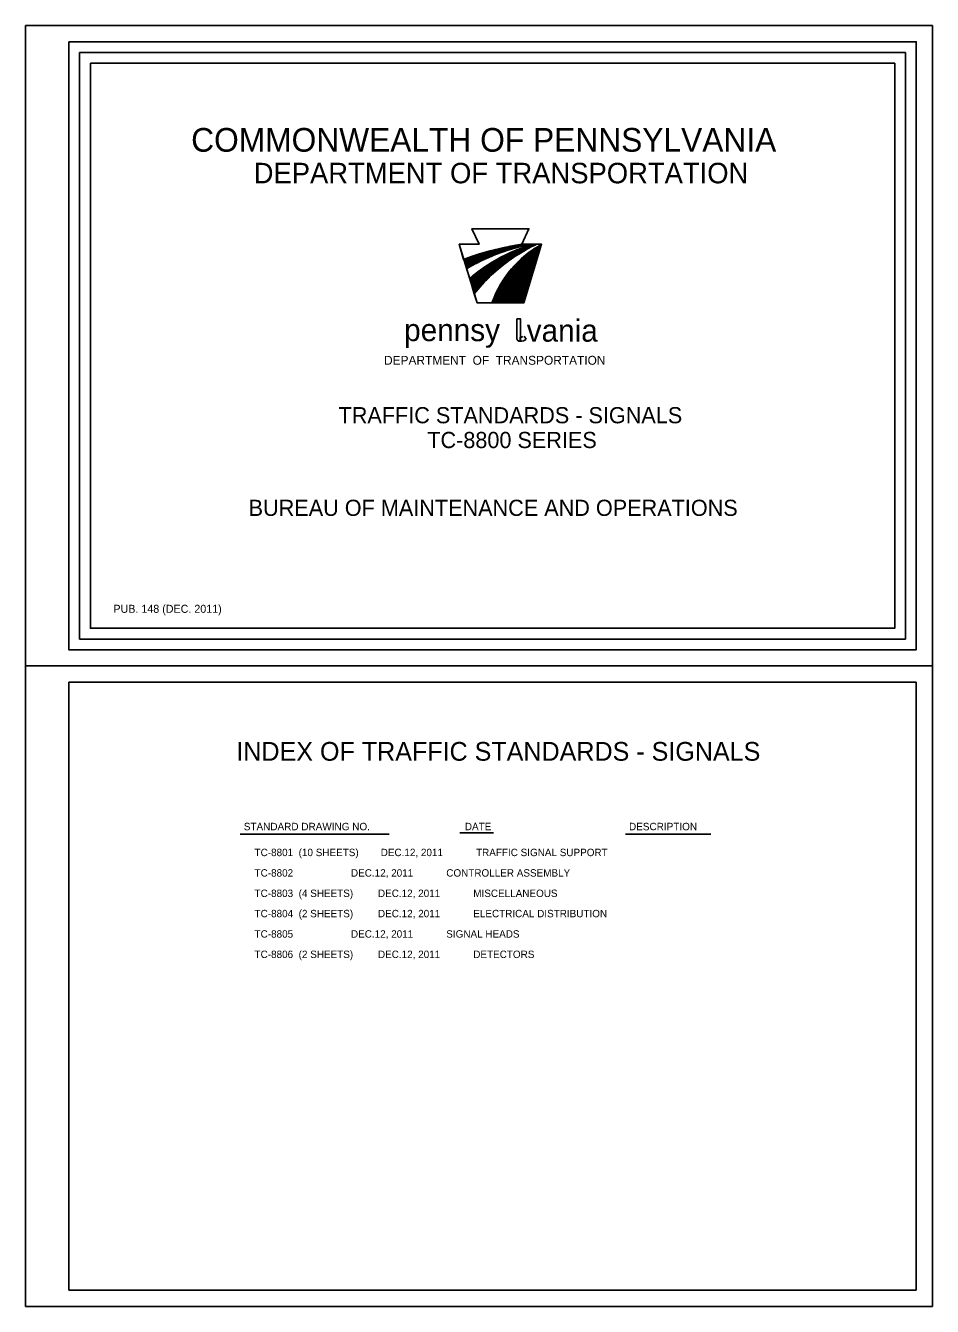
# Model space of a CAD drawing. Extents: x -1746 to -905, y 22 to 1210.
import ezdxf

# ---------------------------------------------------------------- set-up
doc = ezdxf.new("R2010")
doc.units = 0
for name, color, linetype in [('1', 7, 'Continuous'), ('2', 7, 'Continuous'), ('PLT-BNDY', 7, 'Continuous')]:
    doc.layers.add(name, color=color, linetype=linetype)

msp = doc.modelspace()

# ---------------------------------------------------------------- linework, layer by layer
at = {"layer": '1'}
for p, q in [((-1325.5, 1007.3), (-1332.2, 1021.7)), ((-1332.2, 1021.7), (-1279.3, 1021.7)), ((-1279.3, 1021.7), (-1286, 1007.3)), ((-1327.3, 952.9), (-1344, 1007.3)), ((-1344, 1007.3), (-1325.5, 1007.3)), ((-1286, 1007.3), (-1267.6, 1007.3)), ((-1267.6, 1007.3), (-1284.2, 952.9)), ((-1284.2, 952.9), (-1327.3, 952.9)), ((-1706.1, 601.2), (-920.1, 601.2)), ((-1706.1, 37.2), (-1706.1, 601.2)), ((-920.1, 601.2), (-920.1, 37.2)), ((-920.1, 37.2), (-1706.1, 37.2))]:
    msp.add_line(p, q, dxfattribs=at)
for points in [[(-1706.1, 1195.2), (-920.1, 1195.2), (-920.1, 631.2), (-1706.1, 631.2)], [(-1696.1, 1185.2), (-930.1, 1185.2), (-930.1, 641.2), (-1696.1, 641.2)], [(-1686.1, 1175.2), (-940.1, 1175.2), (-940.1, 651.2), (-1686.1, 651.2)], [(-1286, 1007.3), (-1279.3, 1021.7), (-1332.2, 1021.7), (-1325.5, 1007.3), (-1344, 1007.3), (-1340.1, 993.2), (-1332.6, 996), (-1326.2, 998.1), (-1320.9, 999.7), (-1315.2, 1001.2), (-1311, 1002.3), (-1302.4, 1004.3), (-1293.9, 1006), (-1288.6, 1006.8)], [(-1286, 1007.3), (-1289.7, 1006.7), (-1293.9, 1005.9), (-1299, 1004.9), (-1303.4, 1004), (-1308.4, 1002.9), (-1314.9, 1001.2), (-1321.6, 999.4), (-1327.3, 997.6), (-1333.2, 995.7), (-1338, 993.9), (-1339.8, 993.2), (-1337, 984.8), (-1332.7, 987.4), (-1328, 989.8), (-1324.3, 991.7), (-1319.8, 993.9), (-1315.3, 995.8), (-1310.4, 997.8), (-1306.5, 999.3), (-1301.8, 1001), (-1297.2, 1002.4), (-1291.9, 1004), (-1287.6, 1005.2), (-1282.8, 1006.3), (-1279.5, 1007.3)], [(-1279.5, 1007.3), (-1288.1, 1005.1), (-1299.7, 1001.6), (-1309.4, 998.2), (-1318, 994.7), (-1327.6, 990.2), (-1335.1, 986.1), (-1337.3, 984.8), (-1334.2, 975.5), (-1329.9, 979.3), (-1326.8, 981.7), (-1322.8, 984.5), (-1319.5, 986.8), (-1315.6, 989.3), (-1311, 992), (-1305.3, 995.3), (-1300.1, 997.9), (-1294.3, 1000.7), (-1291, 1001.9), (-1286.4, 1003.8), (-1280.6, 1005.7), (-1275.9, 1007.3)], [(-1275.9, 1007.3), (-1281, 1005.6), (-1285.3, 1004.1), (-1290.3, 1002.1), (-1295.5, 1000), (-1300.7, 997.6), (-1306.6, 994.5), (-1312.4, 991.2), (-1317.6, 988), (-1322.4, 984.9), (-1327.4, 981.1), (-1331.1, 978.3), (-1334.2, 975.5), (-1330.1, 961.5), (-1324.9, 967.6), (-1320.4, 972.5), (-1316.2, 976.7), (-1311.3, 981.5), (-1307.1, 985), (-1302.4, 988.9), (-1297.7, 992.5), (-1293.5, 995.4), (-1288.8, 998.3), (-1284.1, 1001.1), (-1280.8, 1003.1), (-1276.6, 1005.4), (-1272.2, 1007.3)], [(-1272.2, 1007.3), (-1276.2, 1005.6), (-1282, 1002.5), (-1289.2, 998.1), (-1297.3, 992.7), (-1304.2, 987.5), (-1308, 984.4), (-1314.3, 978.7), (-1318.1, 974.9), (-1323.2, 969.5), (-1326.5, 965.7), (-1330.1, 961.5), (-1327.3, 952.9), (-1313.4, 952.9), (-1312.6, 955.3), (-1309.9, 961.9), (-1308.2, 965.3), (-1305.3, 970.7), (-1302.6, 975), (-1299, 980.1), (-1295.4, 984.5), (-1290.7, 989.7), (-1286, 994.3), (-1281.9, 997.6), (-1278.1, 1000.7), (-1274.4, 1003.2), (-1270.2, 1005.7), (-1267.6, 1007.3)], [(-1267.6, 1007.3), (-1270.7, 1005.4), (-1274.1, 1003.3), (-1278, 1000.6), (-1282.5, 997.1), (-1286.2, 994.1), (-1289, 991.3), (-1292.4, 987.6), (-1296.4, 983.3), (-1299.7, 979.1), (-1302.6, 975), (-1305.1, 970.9), (-1307, 967.6), (-1309.5, 962.9), (-1312, 956.5), (-1313.4, 952.9), (-1284.2, 952.9)]]:
    msp.add_lwpolyline(points, close=True, dxfattribs=at)
msp.add_circle((-1294.1, 965.8), 6.84, dxfattribs=at)
for centre, radius, start, end in [((-1243, 732.1), 278.5, 98.8803, 110.3962), ((-1239.2, 816.6), 194.6, 102.171, 120.2393), ((-1230.7, 854.8), 159.1, 106.6298, 130.6117), ((-1204.9, 863.2), 159, 115.3724, 141.7165), ((-1219.7, 920.2), 99.4, 118.798, 160.3663)]:
    msp.add_arc(centre, radius, start, end, dxfattribs=at)
at = {"layer": '2'}
for p, q in [((-1338.9, 990.4), (-1325.5, 998.2)), ((-1338.5, 989.5), (-1321.2, 999.5)), ((-1338.2, 988.5), (-1317.4, 1000.5)), ((-1337.9, 987.5), (-1313.6, 1001.5)), ((-1337.6, 986.5), (-1310, 1002.5)), ((-1337.3, 985.6), (-1306.6, 1003.3)), ((-1334, 974.7), (-1279.5, 1006.1)), ((-1333.8, 975.9), (-1284.3, 1004.5)), ((-1333.7, 973.7), (-1275.4, 1007.3)), ((-1333.4, 972.7), (-1282.3, 1002.2)), ((-1329.2, 979.7), (-1290.5, 1002.1)), ((-1326.9, 990.4), (-1303.5, 1003.9)), ((-1322.7, 984.6), (-1298, 998.9)), ((-1316.2, 995.4), (-1300.2, 1004.7)), ((-1309.4, 998.2), (-1297.1, 1005.3)), ((-1303.9, 1000.2), (-1294.1, 1005.9)), ((-1299.2, 1001.8), (-1291.2, 1006.4)), ((-1296.4, 983.3), (-1270.3, 998.3)), ((-1295, 1003.1), (-1288.3, 1006.9)), ((-1294.2, 985.7), (-1269.9, 999.7)), ((-1292, 988.1), (-1269.4, 1001.1)), ((-1290.9, 1004.3), (-1285.6, 1007.3)), ((-1289.6, 990.6), (-1269, 1002.5)), ((-1287, 1005.4), (-1283.6, 1007.3)), ((-1287, 993.3), (-1268.6, 1003.9)), ((-1283.7, 1006.1), (-1281.6, 1007.3)), ((-1282.9, 996.8), (-1268.2, 1005.3)), ((-1279.8, 1003.6), (-1273.4, 1007.3)), ((-1279.6, 1007.3), (-1279.6, 1007.3)), ((-1276.1, 1001.9), (-1267.7, 1006.7)), ((-1339.4, 992.4), (-1334.9, 995)), ((-1339.2, 991.4), (-1330, 996.7)), ((-1333.1, 971.7), (-1299.7, 991)), ((-1332.8, 970.7), (-1305, 986.8)), ((-1306.7, 968.1), (-1273.7, 987.1)), ((-1305.7, 969.8), (-1273.3, 988.5)), ((-1304.7, 971.5), (-1272.9, 989.9)), ((-1303.6, 973.3), (-1272.4, 991.3)), ((-1302.5, 975.1), (-1272, 992.7)), ((-1301.2, 977.1), (-1271.6, 994.1)), ((-1299.8, 979), (-1271.2, 995.5)), ((-1298.1, 981.1), (-1270.7, 996.9)), ((-1332.5, 969.7), (-1309.5, 983)), ((-1332.2, 968.7), (-1313.1, 979.8)), ((-1331.9, 967.8), (-1316, 976.9)), ((-1331.6, 966.8), (-1318.8, 974.2)), ((-1313, 954), (-1277.6, 974.5)), ((-1312.4, 955.5), (-1277.2, 975.9)), ((-1311.8, 957), (-1276.7, 977.3)), ((-1311.2, 958.5), (-1276.3, 978.7)), ((-1310.6, 960.1), (-1275.9, 980.1)), ((-1310, 961.6), (-1275.5, 981.5)), ((-1309.3, 963.1), (-1275, 982.9)), ((-1308.5, 964.7), (-1274.6, 984.3)), ((-1307.6, 966.4), (-1274.2, 985.7)), ((-1331.3, 965.8), (-1321.3, 971.6)), ((-1331, 964.8), (-1323.5, 969.1)), ((-1330.7, 963.8), (-1325.6, 966.8)), ((-1330.4, 962.8), (-1327.6, 964.5)), ((-1312.9, 952.9), (-1278, 973.1)), ((-1310.9, 952.9), (-1278.5, 971.7)), ((-1308.9, 952.9), (-1278.9, 970.3)), ((-1306.9, 952.9), (-1279.3, 968.9)), ((-1304.9, 952.9), (-1279.7, 967.5)), ((-1302.9, 952.9), (-1280.2, 966.1)), ((-1300.9, 952.9), (-1280.6, 964.7)), ((-1298.9, 952.9), (-1281, 963.3)), ((-1330.1, 961.8), (-1329.5, 962.2)), ((-1296.9, 952.9), (-1281.5, 961.9)), ((-1294.9, 952.9), (-1281.9, 960.5)), ((-1292.9, 952.9), (-1282.3, 959.1)), ((-1290.9, 952.9), (-1282.8, 957.7)), ((-1288.9, 952.9), (-1283.2, 956.3)), ((-1286.9, 952.9), (-1283.6, 954.8)), ((-1284.9, 952.9), (-1284, 953.4)), ((-1287.5, 917.5), (-1287.4, 921.1)), ((-1287.4, 921.4), (-1286.8, 920.9)), ((-1287.4, 921.2), (-1287, 920.9)), ((-1283.8, 922.2), (-1282, 919.3)), ((-1547.3, 460.3), (-1409.1, 460.3)), ((-1343.3, 461.3), (-1312.2, 461.3)), ((-1189.9, 460.3), (-1110.5, 460.3)), ((-1533.8, 446.7), (-1533.8, 446.7)), ((-1533.8, 446.5), (-1533.8, 446.5)), ((-1533.8, 427.8), (-1533.8, 427.8)), ((-1533.8, 408.4), (-1533.8, 408.4)), ((-1533.8, 371.1), (-1533.8, 371.1)), ((-1533.8, 352.2), (-1533.8, 352.2))]:
    msp.add_line(p, q, dxfattribs=at)
msp.add_lwpolyline([(-1290.4, 938.2), (-1290.4, 919.5), (-1290, 918.3), (-1288.6, 917.4), (-1287.3, 917.4), (-1287.3, 938.2)], close=True, dxfattribs=at)
for major_axis in [(-7.26, 0), (-2.86, 0)]:
    msp.add_ellipse((-1287.2, 923.2), major_axis=major_axis, ratio=0.782967, start_param=1.534978, end_param=2.37838, dxfattribs=at)
at = {"layer": 'PLT-BNDY'}
for points in [[(-1746.1, 1210.2), (-905.1, 1210.2), (-905.1, 616.2), (-1746.1, 616.2)], [(-1746.1, 616.2), (-905.1, 616.2), (-905.1, 22.2), (-1746.1, 22.2)]]:
    msp.add_lwpolyline(points, close=True, dxfattribs=at)

# ---------------------------------------------------------------- texts
at = {"layer": '2'}
for s, height, p in [('COMMONWEALTH OF PENNSYLVANIA', 22, (-1592.6, 1093.2)), ('DEPARTMENT OF TRANSPORTATION', 19, (-1534.6, 1063.9)), ('vania', 20.63, (-1281.4, 917)), ('pennsy ', 20.63, (-1395.1, 917.5)), ('DEPARTMENT  OF  TRANSPORTATION', 8.25, (-1413.7, 895.6)), ('TRAFFIC STANDARDS - SIGNALS', 15, (-1455.9, 841.3)), ('TC-8800 SERIES', 15, (-1373.6, 818.3)), ('BUREAU OF MAINTENANCE AND OPERATIONS', 15, (-1539.3, 755.4)), ('PUB. 148 (DEC. 2011)', 7.425, (-1664.7, 665.5)), ('INDEX OF TRAFFIC STANDARDS - SIGNALS', 17.397, (-1550.7, 528.3)), ('STANDARD DRAWING NO.', 6.907, (-1543.8, 463.8)), ('DATE', 6.91, (-1338.8, 463.8)), ('DESCRIPTION', 6.907, (-1186.5, 463.8)), ('TC-8801  (10 SHEETS)        DEC.12, 2011            TRAFFIC SIGNAL SUPPORT', 6.875, (-1533.8, 439.8)), ('TC-8802                     DEC.12, 2011            CONTROLLER ASSEMBLY', 6.875, (-1533.8, 420.8)), ('TC-8803  (4 SHEETS)         DEC.12, 2011            MISCELLANEOUS', 6.875, (-1533.8, 401.9)), ('TC-8804  (2 SHEETS)         DEC.12, 2011            ELECTRICAL DISTRIBUTION', 6.875, (-1533.8, 383.1)), ('TC-8805                     DEC.12, 2011            SIGNAL HEADS', 6.875, (-1533.8, 364.2)), ('TC-8806  (2 SHEETS)         DEC.12, 2011            DETECTORS', 6.875, (-1533.8, 345.3))]:
    msp.add_text(s, height=height, dxfattribs=at).set_placement(p)

doc.saveas('drawing.dxf')
